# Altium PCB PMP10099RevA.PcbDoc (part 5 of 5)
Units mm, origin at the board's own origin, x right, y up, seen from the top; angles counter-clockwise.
Board outline 227.58 x 89.92 mm, 2 copper layers (Top Layer, Bottom Layer), stack 1.575 mm thick; 558 components, 261 nets, 1374 pads, 560 vias.
Unrouted connection lines stored in the file: 7.
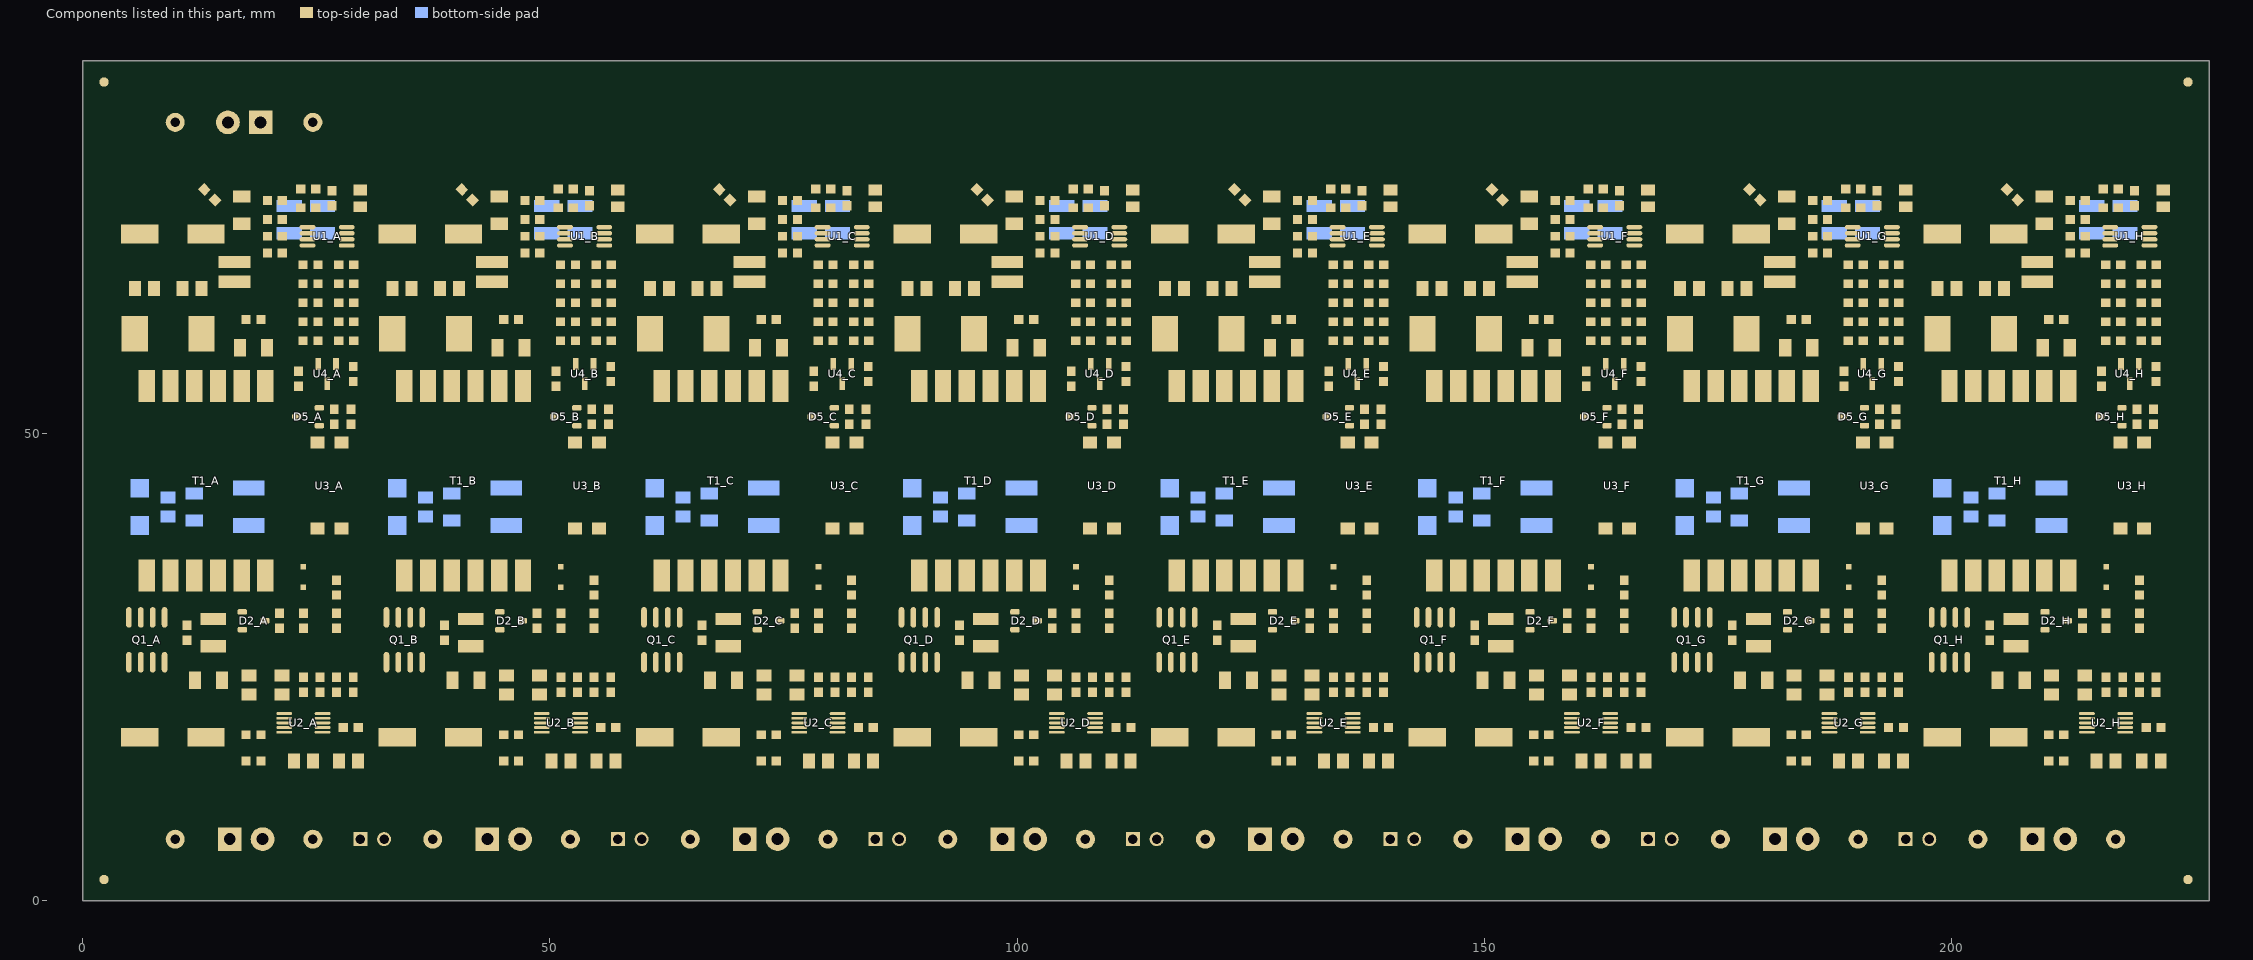
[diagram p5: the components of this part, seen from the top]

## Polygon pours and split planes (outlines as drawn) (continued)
RTN on Top Layer "Top Layer-No Net 18" (solid, remove dead copper, pour order 544): 182.88,3.048 195.834,3.048 195.834,12.446 181.864,12.446 181.864,17.526 175.514,17.526 175.514,9.906 182.88,9.906
VIN on Top Layer "Top Layer-No Net 19" (solid, remove dead copper, pour order 552): 182.372,3.048 182.372,9.398 174.498,9.398 174.498,13.208 169.418,13.208 169.418,3.048
RTN on Top Layer "Top Layer-No Net 13" (solid, remove dead copper, pour order 504): 183.896,36.83 183.896,30.988 185.928,30.988 185.928,30.226 187.452,30.226 187.452,34.544 189.992,34.544 189.992,36.83
NetC11_G_1 on Top Layer "Top Layer-No Net 12" (solid, remove dead copper, pour order 496): 189.992,29.718 185.42,29.718 185.42,30.48 183.896,30.48 183.896,27.94 189.992,27.94
NetC17_G_1 on Top Layer "Top Layer-No Net 15" (solid, remove dead copper, pour order 528): 189.992,30.226 189.992,34.036 187.96,34.036 187.96,30.226
VIN on Top Layer "Top Layer-No Net 14" (solid, remove dead copper, pour order 520): 169.418,21.59 174.498,21.59 174.498,12.954 169.418,12.954
NetD2_G_1 on Top Layer "Top Layer-No Net 11" (solid, remove dead copper, pour order 480): 181.356,36.83 181.356,29.972 183.388,29.972 183.388,36.83
NetQ1_G_4 on Top Layer "Top Layer-No Net 7" (solid, remove dead copper, pour order 416): 173.736,26.67 175.006,26.67 175.768,25.908 175.768,24.384 173.736,24.384
GND on Top Layer "Top Layer-No Net 4" (solid, remove dead copper, pour order 344): 183.896,53.086 186.69,53.086 186.69,66.294 183.896,66.294
NetC6_G_1 on Top Layer "Top Layer-No Net 3" (solid, remove dead copper, pour order 336): 183.388,67.564 183.388,73.406 180.848,73.406 180.848,76.073 179.705,76.073 177.038,73.406 175.006,73.406 175.006,68.58 178.816,68.58 179.832,67.564
GND on Top Layer "Top Layer-No Net 5" (solid, remove dead copper, pour order 352): 174.498,68.58 169.418,68.58 169.418,76.962 180.848,76.962 180.848,76.454 179.578,76.454 177.038,73.914 174.498,73.914
NetC7_G_1 on Top Layer "Top Layer-No Net 2" (solid, remove dead copper, pour order 328): 183.388,57.658 173.99,57.658 173.99,62.738 175.768,62.738 177.292,64.262 177.292,67.056 183.388,67.056
RTN on Top Layer "Top Layer-No Net 16" (solid, remove dead copper, pour order 536): 187.96,19.685 187.96,19.431 185.42,19.431 185.42,19.05 183.388,19.05 183.388,17.272 180.086,17.272 180.086,20.828 185.42,20.828 185.42,19.685
RTN on Top Layer "Top Layer-No Net 10" (solid, remove dead copper, pour order 464): 175.768,28.448 183.642,28.448 183.642,26.416 181.102,26.416 181.102,12.954 175.514,12.954 175.514,21.59 178.562,21.59 178.562,25.908 177.8,26.67 176.276,26.67 175.768,27.178
VIN on Top Layer "Top Layer-No Net 9" (solid, remove dead copper, pour order 448): 175.768,38.608 178.816,38.608 178.816,37.338 178.308,36.83 178.308,32.766 178.562,32.512 181.102,32.512 181.102,28.956 175.768,28.956 175.768,32.512 176.022,32.512 176.276,32.766 176.276,36.83 175.768,37.338
GND on Top Layer "Top Layer-No Net 17" (solid, remove dead copper, pour order 488): 186.69,53.594 186.69,46.482 185.166,44.958 181.102,44.958 181.102,48.26 183.896,51.054 183.896,53.594
NetD1_G_2 on Top Layer "Top Layer-No Net 6" (solid, remove dead copper, pour order 392): 173.228,38.608 173.228,32.766 173.482,32.512 174.752,32.512 174.752,28.448 169.672,28.448 169.672,32.512 170.18,32.512 170.434,32.766 170.434,38.608
NetQ1_G_1 on Top Layer "Top Layer-No Net 8" (solid, remove dead copper, pour order 432): 173.228,27.432 173.228,24.13 173.482,23.876 176.022,23.876 176.276,24.13 176.276,25.908 178.054,25.908 178.054,22.098 169.672,22.098 169.672,27.432
RTN on Top Layer "Top Layer-No Net 20" (solid, remove dead copper, pour order 296): 187.452,40.64 187.452,37.338 190.5,37.338 190.5,26.416 189.865,25.781 189.865,23.368 195.199,23.368 195.199,40.64
GND on Top Layer "Top Layer-No Net 21" (solid, remove dead copper, pour order 304): 195.326,48.26 195.326,67.056 187.198,67.056 187.198,48.26
NetC5_H_1 on Top Layer "Top Layer-No Net 1" (solid, remove dead copper, pour order 319): 199.771,67.056 204.343,67.056 204.343,64.516 204.089,64.262 200.025,64.262 199.771,64.516
NetC5_H_2 on Top Layer "Top Layer-No Net" (solid, remove dead copper, pour order 311): 200.787,53.086 200.787,62.738 199.263,64.262 199.263,67.056 196.977,67.056 196.977,53.086
RTN on Top Layer "Top Layer-No Net 18" (solid, remove dead copper, pour order 543): 210.439,3.048 223.393,3.048 223.393,12.446 209.423,12.446 209.423,17.526 203.073,17.526 203.073,9.906 210.439,9.906
VIN on Top Layer "Top Layer-No Net 19" (solid, remove dead copper, pour order 551): 209.931,3.048 209.931,9.398 202.057,9.398 202.057,13.208 196.977,13.208 196.977,3.048
RTN on Top Layer "Top Layer-No Net 13" (solid, remove dead copper, pour order 503): 211.455,36.83 211.455,30.988 213.487,30.988 213.487,30.226 215.011,30.226 215.011,34.544 217.551,34.544 217.551,36.83
NetC11_H_1 on Top Layer "Top Layer-No Net 12" (solid, remove dead copper, pour order 495): 217.551,29.718 212.979,29.718 212.979,30.48 211.455,30.48 211.455,27.94 217.551,27.94
NetC17_H_1 on Top Layer "Top Layer-No Net 15" (solid, remove dead copper, pour order 527): 217.551,30.226 217.551,34.036 215.519,34.036 215.519,30.226
VIN on Top Layer "Top Layer-No Net 14" (solid, remove dead copper, pour order 519): 196.977,21.59 202.057,21.59 202.057,12.954 196.977,12.954
NetD2_H_1 on Top Layer "Top Layer-No Net 11" (solid, remove dead copper, pour order 479): 208.915,36.83 208.915,29.972 210.947,29.972 210.947,36.83
NetQ1_H_4 on Top Layer "Top Layer-No Net 7" (solid, remove dead copper, pour order 415): 201.295,26.67 202.565,26.67 203.327,25.908 203.327,24.384 201.295,24.384
GND on Top Layer "Top Layer-No Net 4" (solid, remove dead copper, pour order 343): 211.455,53.086 214.249,53.086 214.249,66.294 211.455,66.294
NetC6_H_1 on Top Layer "Top Layer-No Net 3" (solid, remove dead copper, pour order 335): 210.947,67.564 210.947,73.406 208.407,73.406 208.407,76.073 207.264,76.073 204.597,73.406 202.565,73.406 202.565,68.58 206.375,68.58 207.391,67.564
GND on Top Layer "Top Layer-No Net 5" (solid, remove dead copper, pour order 351): 202.057,68.58 196.977,68.58 196.977,76.962 208.407,76.962 208.407,76.454 207.137,76.454 204.597,73.914 202.057,73.914
NetC7_H_1 on Top Layer "Top Layer-No Net 2" (solid, remove dead copper, pour order 327): 210.947,57.658 201.549,57.658 201.549,62.738 203.327,62.738 204.851,64.262 204.851,67.056 210.947,67.056
RTN on Top Layer "Top Layer-No Net 16" (solid, remove dead copper, pour order 535): 215.519,19.685 215.519,19.431 212.979,19.431 212.979,19.05 210.947,19.05 210.947,17.272 207.645,17.272 207.645,20.828 212.979,20.828 212.979,19.685
RTN on Top Layer "Top Layer-No Net 10" (solid, remove dead copper, pour order 463): 203.327,28.448 211.201,28.448 211.201,26.416 208.661,26.416 208.661,12.954 203.073,12.954 203.073,21.59 206.121,21.59 206.121,25.908 205.359,26.67 203.835,26.67 203.327,27.178
VIN on Top Layer "Top Layer-No Net 9" (solid, remove dead copper, pour order 447): 203.327,38.608 206.375,38.608 206.375,37.338 205.867,36.83 205.867,32.766 206.121,32.512 208.661,32.512 208.661,28.956 203.327,28.956 203.327,32.512 203.581,32.512 203.835,32.766 203.835,36.83 203.327,37.338
GND on Top Layer "Top Layer-No Net 17" (solid, remove dead copper, pour order 487): 214.249,53.594 214.249,46.482 212.725,44.958 208.661,44.958 208.661,48.26 211.455,51.054 211.455,53.594
NetD1_H_2 on Top Layer "Top Layer-No Net 6" (solid, remove dead copper, pour order 391): 200.787,38.608 200.787,32.766 201.041,32.512 202.311,32.512 202.311,28.448 197.231,28.448 197.231,32.512 197.739,32.512 197.993,32.766 197.993,38.608
NetQ1_H_1 on Top Layer "Top Layer-No Net 8" (solid, remove dead copper, pour order 431): 200.787,27.432 200.787,24.13 201.041,23.876 203.581,23.876 203.835,24.13 203.835,25.908 205.613,25.908 205.613,22.098 197.231,22.098 197.231,27.432
RTN on Top Layer "Top Layer-No Net 20" (solid, remove dead copper, pour order 295): 215.011,40.64 215.011,37.338 218.059,37.338 218.059,26.416 217.424,25.781 217.424,23.368 222.758,23.368 222.758,40.64
GND on Top Layer "Top Layer-No Net 21" (solid, remove dead copper, pour order 303): 222.885,48.26 222.885,67.056 214.757,67.056 214.757,48.26
NetC5_B_1 on Top Layer "Top Layer-No Net 1" (solid, remove dead copper, pour order 318): 34.417,67.056 38.989,67.056 38.989,64.516 38.735,64.262 34.671,64.262 34.417,64.516
NetC5_B_2 on Top Layer "Top Layer-No Net" (solid, remove dead copper, pour order 310): 35.433,53.086 35.433,62.738 33.909,64.262 33.909,67.056 31.623,67.056 31.623,53.086
RTN on Top Layer "Top Layer-No Net 18" (solid, remove dead copper, pour order 542): 45.085,3.048 58.039,3.048 58.039,12.446 44.069,12.446 44.069,17.526 37.719,17.526 37.719,9.906 45.085,9.906
VIN on Top Layer "Top Layer-No Net 19" (solid, remove dead copper, pour order 550): 44.577,3.048 44.577,9.398 36.703,9.398 36.703,13.208 31.623,13.208 31.623,3.048
RTN on Top Layer "Top Layer-No Net 13" (solid, remove dead copper, pour order 502): 46.101,36.83 46.101,30.988 48.133,30.988 48.133,30.226 49.657,30.226 49.657,34.544 52.197,34.544 52.197,36.83
NetC11_B_1 on Top Layer "Top Layer-No Net 12" (solid, remove dead copper, pour order 494): 52.197,29.718 47.625,29.718 47.625,30.48 46.101,30.48 46.101,27.94 52.197,27.94
NetC17_B_1 on Top Layer "Top Layer-No Net 15" (solid, remove dead copper, pour order 526): 52.197,30.226 52.197,34.036 50.165,34.036 50.165,30.226
VIN on Top Layer "Top Layer-No Net 14" (solid, remove dead copper, pour order 518): 31.623,21.59 36.703,21.59 36.703,12.954 31.623,12.954
NetD2_B_1 on Top Layer "Top Layer-No Net 11" (solid, remove dead copper, pour order 478): 43.561,36.83 43.561,29.972 45.593,29.972 45.593,36.83
NetQ1_B_4 on Top Layer "Top Layer-No Net 7" (solid, remove dead copper, pour order 414): 35.941,26.67 37.211,26.67 37.973,25.908 37.973,24.384 35.941,24.384
GND on Top Layer "Top Layer-No Net 4" (solid, remove dead copper, pour order 342): 46.101,53.086 48.895,53.086 48.895,66.294 46.101,66.294
NetC6_B_1 on Top Layer "Top Layer-No Net 3" (solid, remove dead copper, pour order 334): 45.593,67.564 45.593,73.406 43.053,73.406 43.053,76.073 41.91,76.073 39.243,73.406 37.211,73.406 37.211,68.58 41.021,68.58 42.037,67.564
GND on Top Layer "Top Layer-No Net 5" (solid, remove dead copper, pour order 350): 36.703,68.58 31.623,68.58 31.623,76.962 43.053,76.962 43.053,76.454 41.783,76.454 39.243,73.914 36.703,73.914
NetC7_B_1 on Top Layer "Top Layer-No Net 2" (solid, remove dead copper, pour order 326): 45.593,57.658 36.195,57.658 36.195,62.738 37.973,62.738 39.497,64.262 39.497,67.056 45.593,67.056
RTN on Top Layer "Top Layer-No Net 16" (solid, remove dead copper, pour order 534): 50.165,19.685 50.165,19.431 47.625,19.431 47.625,19.05 45.593,19.05 45.593,17.272 42.291,17.272 42.291,20.828 47.625,20.828 47.625,19.685
RTN on Top Layer "Top Layer-No Net 10" (solid, remove dead copper, pour order 462): 37.973,28.448 45.847,28.448 45.847,26.416 43.307,26.416 43.307,12.954 37.719,12.954 37.719,21.59 40.767,21.59 40.767,25.908 40.005,26.67 38.481,26.67 37.973,27.178
VIN on Top Layer "Top Layer-No Net 9" (solid, remove dead copper, pour order 446): 37.973,38.608 41.021,38.608 41.021,37.338 40.513,36.83 40.513,32.766 40.767,32.512 43.307,32.512 43.307,28.956 37.973,28.956 37.973,32.512 38.227,32.512 38.481,32.766 38.481,36.83 37.973,37.338
GND on Top Layer "Top Layer-No Net 17" (solid, remove dead copper, pour order 486): 48.895,53.594 48.895,46.482 47.371,44.958 43.307,44.958 43.307,48.26 46.101,51.054 46.101,53.594
NetD1_B_2 on Top Layer "Top Layer-No Net 6" (solid, remove dead copper, pour order 390): 35.433,38.608 35.433,32.766 35.687,32.512 36.957,32.512 36.957,28.448 31.877,28.448 31.877,32.512 32.385,32.512 32.639,32.766 32.639,38.608
NetQ1_B_1 on Top Layer "Top Layer-No Net 8" (solid, remove dead copper, pour order 430): 35.433,27.432 35.433,24.13 35.687,23.876 38.227,23.876 38.481,24.13 38.481,25.908 40.259,25.908 40.259,22.098 31.877,22.098 31.877,27.432
RTN on Top Layer "Top Layer-No Net 20" (solid, remove dead copper, pour order 294): 49.657,40.64 49.657,37.338 52.705,37.338 52.705,26.416 52.07,25.781 52.07,23.368 57.404,23.368 57.404,40.64
GND on Top Layer "Top Layer-No Net 21" (solid, remove dead copper, pour order 302): 57.531,48.26 57.531,67.056 49.403,67.056 49.403,48.26
VOUT on Top Layer "Top Overlay-No Net" (solid, remove dead copper, pour order 292): 16.002,74.422 18.034,74.422 18.034,86.868 16.002,86.868
VOUT on Top Layer "Top Overlay-No Net" (solid, remove dead copper, pour order 565): 43.561,74.422 45.593,74.422 45.593,86.868 43.561,86.868
VOUT on Top Layer "Top Overlay-No Net" (solid, remove dead copper, pour order 566): 71.12,74.422 73.152,74.422 73.152,86.868 71.12,86.868
VOUT on Top Layer "Top Overlay-No Net" (solid, remove dead copper, pour order 567): 98.679,74.422 100.711,74.422 100.711,86.868 98.679,86.868
VOUT on Top Layer "Top Overlay-No Net" (solid, remove dead copper, pour order 568): 126.238,74.422 128.27,74.422 128.27,86.868 126.238,86.868
VOUT on Top Layer "Top Overlay-No Net" (solid, remove dead copper, pour order 569): 153.797,74.422 155.829,74.422 155.829,86.868 153.797,86.868
VOUT on Top Layer "Top Overlay-No Net" (solid, remove dead copper, pour order 570): 181.356,74.422 183.388,74.422 183.388,86.868 181.356,86.868
VOUT on Top Layer "Top Overlay-No Net" (solid, remove dead copper, pour order 571): 208.915,74.422 210.947,74.422 210.947,86.868 208.915,86.868
VOUT on Top Layer "Top Layer-No Net 22" (solid, pour order 572): 4.064,86.868 4.064,78.74 223.393,78.74 223.393,86.868

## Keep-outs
Keep-Out Layer:
  text ".Layer_Name" at 14.656,-21.806 h1.52

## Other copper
Top Layer:
  text ".Layer_Name" at 14.656,-21.806 h1.52
Bottom Layer:
  text ".Layer_Name" at 14.656,-21.806 h1.52

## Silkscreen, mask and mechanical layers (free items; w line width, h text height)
Top Overlay:
  lines w0.178: 3.81,12.446 30.734,12.446 30.734,77.216 3.81,77.216 3.81,12.446 ; 31.369,12.446 31.369,77.216 58.293,77.216 58.293,12.446 31.369,12.446 ; 58.928,12.446 58.928,77.216 85.852,77.216 85.852,12.446 58.928,12.446 ; 86.487,12.446 86.487,77.216 113.411,77.216 113.411,12.446 86.487,12.446 ; 114.046,12.446 114.046,77.216 140.97,77.216 140.97,12.446 114.046,12.446 ; 141.605,12.446 141.605,77.216 168.529,77.216 168.529,12.446 141.605,12.446 ; 169.164,12.446 169.164,77.216 196.088,77.216 196.088,12.446 169.164,12.446 ; 196.723,12.446 196.723,77.216 223.647,77.216 223.647,12.446 196.723,12.446
  text ".Layer_Name" at 14.656,-21.806 h1.52
Bottom Overlay:
  text ".Layer_Name" at 14.656,-21.806 h1.52
Top Paste:
  text ".Layer_Name" at 14.656,-21.806 h1.52
Bottom Paste:
  text ".Layer_Name" at 14.656,-21.806 h1.52
Top Solder:
  text "PMP10099" at 202.184,82.296 h2.54
  text ".Layer_Name" at 14.656,-21.806 h1.52
  text ".Layer_Name" at 14.656,-21.806 h1.52
Bottom Solder:
  circle w0.254: c219.329,82.804 r2.032
  circle w0.381: c220.218,83.439 r0.127
  circle w0.381: c218.567,83.439 r0.127
  lines w0.254: 218.227,81.915 218.481,82.169 ; 218.399,82.042 ccw(c219.372,82.858) 220.345,82.042 ; 220.218,82.169 220.472,81.915
  text ".Layer_Name" at 14.656,-21.806 h1.52
Drill Guide:
  text ".Layer_Name" at 14.656,-21.806 h1.52
M1 Board Outline:
  lines w0.5: -0.25,0 ccw(c0,0) 0,-0.25 ; -0.25,0 ccw(c0,0) 0,-0.25 ; -0.25,0 -0.25,89.916 ; -0.25,89.916 cw(c0,89.916) 0,90.166 ; -0.25,89.916 cw(c0,89.916) 0,90.166 ; 0,-0.25 227.584,-0.25 ; 0,90.166 227.584,90.166 ; 227.584,-0.25 ccw(c227.584,0) 227.834,0 ; 227.584,-0.25 ccw(c227.584,0) 227.834,0 ; 227.584,90.166 cw(c227.584,89.916) 227.834,89.916 ; 227.584,90.166 cw(c227.584,89.916) 227.834,89.916 ; 227.834,0 227.834,89.916
  text ".Layer_Name" at 14.656,-21.806 h1.52
M2 Board Dimensions:
  text ".Layer_Name" at 14.656,-21.806 h1.52
M3 3D STEP Top:
  text ".Layer_Name" at 14.656,-21.806 h1.52
M4 3D STEP Bottom:
  text ".Layer_Name" at 14.656,-21.806 h1.52
M5 Assembly Top:
  lines w0.254: -7.417,-23.626 160.223,-23.626 ; -7.417,-18.462 160.274,-18.462 ; -7.417,-13.297 -7.417,-28.791 94.31,-28.791 160.274,-28.791 160.274,-13.297 -7.404,-13.297 -7.404,-28.791 32.614,-28.791 ; 55.194,-28.791 55.194,-13.297 ; 87.376,-18.462 87.376,-13.297 ; 108.712,-18.462 108.712,-13.297 ; 124.511,-28.956 124.511,-23.804
  text "PCB VIEWED FROM TOP SIDE" at -5.804,-16.654 h1.52
  text "BOARD #:" at 57.099,-16.654 h1.52
  text ".PRJ_Number" at 70.955,-16.654 h1.52
  text "REV:" at 92.405,-16.654 h1.52
  text ".PCB_Rev" at 99.809,-16.654 h1.52
  text "SVN REV:" at 113.69,-16.654 h1.52
  text ".VersionControl_RevNumber" at 126.543,-16.654 h1.52
  text "IGNORE ->" at -5.804,-21.806 h1.52
  text "PLOT NAME =" at -5.804,-27.034 h1.52
  text ".plot_File_Name" at 14.656,-27.034 h1.52
  text "GENERATED    :" at 57.15,-27.034 h1.52
  text ".Print_Date" at 79.235,-27.034 h1.52
  text ".Print_Time" at 97.752,-27.034 h1.52
  text "TEXAS INSTRUMENTS" at 129.87,-27.034 h1.52
M6 Assembly Bottom:
  lines w0.254: -7.429,-18.474 160.261,-18.474 ; -7.379,-23.639 160.261,-23.639 ; 28.334,-28.969 28.334,-23.817 ; 44.133,-18.474 44.133,-13.31 ; 65.468,-18.474 65.468,-13.31 ; 97.65,-28.804 97.65,-13.31 ; 120.231,-28.804 160.249,-28.804 160.249,-13.31 -7.429,-13.31 -7.429,-28.804 58.534,-28.804 160.261,-28.804 160.261,-13.31
  text ".VersionControl_RevNumber" at 26.302,-16.667 h1.52
  text "SVN REV:" at 39.154,-16.667 h1.52
  text ".PCB_Rev" at 53.035,-16.667 h1.52
  text "REV:" at 60.439,-16.667 h1.52
  text ".PRJ_Number" at 81.89,-16.667 h1.52
  text "BOARD #:" at 95.745,-16.667 h1.52
  text "PCB VIEWED FROM BOTTOM SIDE" at 158.648,-16.667 h1.52
  text "IGNORE ->" at 64.715,-21.806 h1.52
  text "TEXAS INSTRUMENTS" at 22.974,-27.047 h1.52
  text ".Print_Time" at 55.093,-27.047 h1.52
  text ".Print_Date" at 73.609,-27.047 h1.52
  text "GENERATED    :" at 95.694,-27.047 h1.52
  text ".plot_File_Name" at 138.189,-27.047 h1.52
  text "PLOT NAME =" at 158.648,-27.047 h1.52
M9 Title Sheet:
  drawing of 57 lines, arcs and shapes, not listed
  text "1" at 18.792,204.127 h1.78
  text "2" at 82.182,204.127 h1.78
  text "3" at 145.411,204.127 h1.78
  text "4" at 209.08,204.127 h1.78
  text "5" at 272.555,204.127 h1.78
  text "6" at 336.182,204.127 h1.78
  text "A" at -10.579,175.095 h1.78
  text "A" at 365.341,175.095 h1.78
  text "B" at -10.579,114.643 h1.78
  text "B" at 365.341,114.643 h1.78
  text "C" at -10.579,54.318 h1.78
  text "C" at 365.341,54.318 h1.78
  text "PROJECT TITLE:" at 288.125,7.048 h1.14
  text ".PRJ_Title" at 289.395,3.662 h1.78
  text "DESIGNED FOR:" at 288.125,-0.597 h1.14
  text ".PRJ_Customer" at 289.395,-4.153 h1.78
  text "D" at -10.579,-5.88 h1.78
  text "D" at 365.341,-5.88 h1.78
  text "FILE NAME:" at 288.125,-8.217 h1.14
  text ".PCB_File_Name_No_Path" at 289.395,-11.265 h1.78
  text "Texas Instruments (TI) and/or its licensors do not warrant the accuracy or completeness of this specification" at 161.9,-15.376 h1.14
  text "ENGINEER:" at 288.125,-15.583 h1.14
  text "LAYOUT BY:" at 326.352,-15.583 h1.14
  text "or any information contained therein. TI and/or its licensors do not warrant that this design will meet" at 160.757,-18.237 h1.14
  text ".PRJ_Engineer" at 289.395,-19.52 h1.78
  text ".PCB_Layout" at 327.635,-19.52 h1.78
  text "the specifications, will be suitable for your application or fit for any particular purpose, or will operate in" at 160.757,-21.099 h1.14
  text ".Layer_Name" at 14.656,-21.806 h1.52
  text "ALTIUM DESIGNER VERSION:" at 326.352,-23.457 h1.14
  text "an implementation. TI and/or its licensors do not warrant that the design is production worthy. You should" at 160.757,-23.961 h1.14
  text "completely validate and test your design implementation to confirm the system functionality for your application." at 161.9,-26.822 h1.14
  text ".print_Scale" at 289.395,-26.843 h1.78
  text ".Application_BuildNumber" at 327.635,-26.843 h1.78
  text "1" at 18.792,-32.093 h1.78
  text "2" at 82.182,-32.093 h1.78
  text "3" at 145.411,-32.093 h1.78
  text "4" at 209.08,-32.093 h1.78
  text "5" at 272.555,-32.093 h1.78
  text "6" at 336.182,-32.093 h1.78
M10 Fab Notes:
  drawing of 212 lines, arcs and shapes, not listed
  text "DESIGN INFORMATION" at 314.478,172.974 h1.52
  text "(REFER ALSO ARRAY/PANEL PROFILING INFORMATION)" at 305.294,168.866 h1.52
  text "BOARD SIZE" at 287.87,168.758 h1.52
  text "3450MIL" at 299.613,165.511 h1.52
  text "4950MIL" at 318.333,165.511 h1.52
  text "Number of Layers :" at 298.106,160.503 h1.52
  text "2" at 325.914,160.249 h1.52
  text "MIN. TRACK WIDTH:" at 298.106,156.972 h1.52
  text "8" at 325.951,156.972 h1.52
  text "MIL" at 329.881,156.972 h1.52
  text "MIN. CLEARANCE:" at 298.106,153.619 h1.52
  text "8" at 325.951,153.619 h1.52
  text "MIL" at 329.881,153.619 h1.52
  text "MIN. VIA PAD SIZE:" at 298.106,150.266 h1.52
  text "24" at 325.189,150.266 h1.52
  text "MIL" at 329.881,150.266 h1.52
  text "0.05mm (2MIL)" at 315.759,146.667 h1.52
  text "MINIMUM ANNULAR RING" at 289.744,146.558 h1.52
  text "EXTERNAL" at 333.742,146.558 h1.52
  text "PER" at 294.824,143.561 h1.52
  text "IPC-D-275 CLASS 2 LEVEL C" at 300.412,143.561 h1.52
  text "MIL, HOLES" at 338.213,140.709 h1.52
  text "+/-" at 328.244,140.691 h1.52
  text "+/-" at 349.936,140.691 h1.52
  text "REGISTRATION TOLERANCES:" at 289.744,140.564 h1.52
  text "METAL" at 320.218,140.564 h1.52
  text "5" at 334.853,140.564 h1.52
  text "3" at 356.012,140.564 h1.52
  text "MIL" at 358.964,140.564 h1.52
  text "MATERIAL:" at 287.844,135.243 h1.52
  text "FR-4 High Tg" at 312.9,131.679 h1.52
  text "FR-408" at 298.538,131.461 h1.52
  text "OTHER" at 336.333,131.461 h1.52
  text "62 MIL (1.6mm) +/-10%" at 306.668,127.328 h1.52
  text "THICKNESS:" at 289.744,127.219 h1.52
  text "OTHER" at 339.305,127.219 h1.52
  text "TOLERANCE:" at 289.744,123.206 h1.52
  text "ANSI IPC-6012 TYPE 3 CLASS 2" at 315.81,123.206 h1.52
  text "OTHER +/-" at 315.81,119.244 h1.52
  text "BOW & TWIST:" at 289.744,115.256 h1.52
  text "ANSI IPC-6012 TYPE 3 CLASS 2" at 315.81,115.256 h1.52
  text "OTHER +/-" at 315.81,111.23 h1.52
  text "COPPER THICKNESS (FINISHED):" at 287.844,107.788 h1.52
  text "1.4MIL (1oz)" at 310.196,103.909 h1.52
  text "2MIL (1.4oz)" at 329.678,103.909 h1.52
  text "2.8MIL (2oz)" at 348.144,103.909 h1.52
  text "OUTER:" at 296.912,103.801 h1.52
  text "1.4MIL (1oz)" at 310.196,99.922 h1.52
  text "2.8MIL (2oz)" at 329.678,99.922 h1.52
  text "N/A" at 348.132,99.931 h1.52
  text "INNER SIGNAL:" at 289.57,99.813 h1.52
  text "DRILLING:" at 287.844,96.282 h1.52
  text "REFERENCE:" at 289.744,93.31 h1.52
  text "AS SHOWN" at 310.958,93.31 h1.52
  text "NC_DRILL FILES" at 332.574,93.31 h1.52
  text "PTH MIN COPPER THICKNESS:" at 289.744,89.297 h1.52
  text "1MIL" at 327.519,89.297 h1.52
  text "OTHER" at 340.143,89.297 h1.52
  text "BOARD FINISH:" at 287.844,85.259 h1.52
  text "SILKSCREEN:" at 291.787,82.261 h1.52
  text "TOP" at 319.086,82.261 h1.52
  text "BOTTOM" at 332.066,82.261 h1.52
  text "SILKSCREEN COLOR:" at 291.787,78.02 h1.52
  text "WHITE" at 319.086,78.02 h1.52
  text "OTHER" at 332.066,78.02 h1.52
  text "SOLDER RESIST COLOR:" at 291.787,73.702 h1.52
  text "X" at 212.72,73.24 h1.52 r90
  text "X" at 148.091,71.845 h1.52 r90
  text "X" at 156.041,71.845 h1.52 r90
  text "X" at 175.65,71.845 h1.52 r90
  text "X" at 183.6,71.845 h1.52 r90
  text "X" at 99.603,70.828 h1.52 r90
  text "X" at 193.303,69.785 h1.52 r90
  text "GREEN" at 309.434,69.658 h1.52
  text "BLUE" at 324.446,69.658 h1.52
  text "OTHER" at 338.111,69.658 h1.52
  text "X" at 118.018,67.753 h1.52 r90
  text "X" at 167.513,67.716 h1.52 r90
  text "X" at 195.072,67.716 h1.52 r90
  text "X" at 94.705,66.991 h1.52 r90
  text "X" at 124.52,66.991 h1.52 r90
  text "IMMERSION GOLD (ENIG)" at 314.794,64.87 h1.52
  text "ENEPIG" at 348.767,64.786 h1.52
  text "SURFACE FINISH:" at 287.844,64.761 h1.52
  text "X" at 144.078,64.196 h1.52 r90
  text "X" at 171.637,64.196 h1.52 r90
  text "IMM. TIN/SILVER OR EQUIV" at 296.215,60.773 h1.52
  text "OTHER" at 332.574,60.773 h1.52
  text "X" at 72.12,57.608 h1.52 r90
  text "X" at 99.679,57.608 h1.52 r90
  text "X" at 68.069,57.555 h1.52 r90
  text "X" at 95.628,57.555 h1.52 r90
  text "ARRAY/PANEL:" at 287.844,56.226 h1.52
  text "CUT AND TRIM PER MECH LAYER 1" at 314.794,56.118 h1.52
  text "N.C. ROUTE" at 314.794,52.264 h1.52
  text "V. SCORE" at 336.79,52.264 h1.52
  text "CERTIFICATION:" at 287.844,48.784 h1.52
  text "MATERIALS AND WORKMANSHIP FOR ALL PCBS" at 306.259,48.784 h1.52
  text "TO MEET OR EXCEED THE REQUIREMENTS OF:" at 306.259,46.295 h1.52
  text "ANSI IPC-A-600F CLASS ->" at 300.303,42.828 h1.52
  text "2" at 344.956,42.828 h1.52
  text "1" at 336.955,42.79 h1.52
  text "3" at 353.948,42.79 h1.52
  text "UL 94V-0" at 300.303,38.777 h1.52
  text "RoHS" at 320.928,38.777 h1.52
  text "OTHER" at 337.296,38.777 h1.52
  text "PER ORDER" at 347.381,38.777 h1.52
  text "ADDITIONAL REQUIREMENTS:" at 287.844,35.195 h1.52
  text "MICROSECTION:" at 289.744,32.274 h1.52
  text "YES" at 312.749,32.274 h1.52
  text "REQUIRED" at 334.631,28.308 h1.52
  text "BARE BOARD ELEC. TEST:" at 289.744,28.236 h1.52
  text "NONE" at 322.909,28.236 h1.52
  text "PER ORDER" at 349.668,28.236 h1.52
  text "MANUFACTURER'S UL:" at 289.744,24.248 h1.52
  text "RAIL" at 319.353,24.139 h1.52
  text "METAL" at 331.845,24.139 h1.52
  text "SILK" at 344.842,24.139 h1.52
  text ".Layer_Name" at 14.656,-21.806 h1.52
M11 Gerber Information:
  lines w0.254: -7.417,-23.626 160.223,-23.626 ; -7.417,-18.462 160.274,-18.462 ; -7.417,-13.297 -7.417,-28.791 94.31,-28.791 160.274,-28.791 160.274,-13.297 -7.404,-13.297 -7.404,-28.791 32.614,-28.791 ; 55.194,-28.791 55.194,-13.297 ; 87.376,-18.462 87.376,-13.297 ; 108.712,-18.462 108.712,-13.297 ; 124.511,-28.956 124.511,-23.804
  text "ALL ARTWORK VIEWED FROM TOP SIDE" at -5.804,-16.654 h1.52
  text "BOARD #:" at 57.099,-16.654 h1.52
  text ".PRJ_Number" at 70.955,-16.654 h1.52
  text "REV:" at 92.405,-16.654 h1.52
  text ".PCB_Rev" at 99.809,-16.654 h1.52
  text "SVN REV:" at 113.69,-16.654 h1.52
  text ".VersionControl_RevNumber" at 126.543,-16.654 h1.52
  text "LAYER NAME =" at -5.804,-21.806 h1.52
  text "PLOT NAME =" at -5.804,-27.034 h1.52
  text ".plot_File_Name" at 14.656,-27.034 h1.52
  text "GENERATED    :" at 57.15,-27.034 h1.52
  text ".Print_Date" at 79.235,-27.034 h1.52
  text ".Print_Time" at 97.752,-27.034 h1.52
  text "TEXAS INSTRUMENTS" at 129.87,-27.034 h1.52
M12 Stackup:
  lines w0.152: 201.066,47.803 ccw(c201.066,48.666) 201.93,48.666 ; 261.804,178.689 261.804,196.621 cw(c262.668,196.621) 262.668,197.485 ; 287.884,195.961 353.974,195.961 cw(c353.974,195.097) 354.838,195.097 354.838,177.165 ; 288.544,189.484 353.314,189.484 ; 288.544,192.136 353.314,192.136
  text "The Stackup Legend below this is static." at 294.78,200.012 h1.52
  text "If you change the stackup, update the Legend." at 295.034,197.726 h1.52
  text "Layer Stack Up Detail for: Ref_Design.PcbDoc" at 288.544,192.966 h1.45
  text "Layer" at 263.328,192.669 h0.61
  text "Name" at 263.328,191.45 h0.61
  text "Gerber" at 311.298,191.145 h0.61
  text "Copper" at 325.611,191.145 h0.61
  text "Dielectric" at 340.92,191.145 h0.61
  text "Document" at 311.298,189.926 h0.61
  text "Thickness" at 325.611,189.926 h0.61
  text "Material" at 340.92,189.926 h0.61
  text "Top Solder Mask" at 288.544,187.565 h0.86
  text "(.GTS)" at 311.298,187.565 h0.86
  text "Solder Resist" at 340.92,187.565 h0.86
  text "Top Layer" at 263.328,186.631 h0.86
  text "(.GTL)" at 311.298,185.107 h0.86
  text "1.4mil" at 325.611,185.107 h0.86
  text "FR-4" at 340.92,183.879 h0.86
  text "Bottom Layer" at 288.544,182.65 h0.86
  text "(.GBL)" at 311.298,182.65 h0.86
  text "1.4mil" at 325.611,182.65 h0.86
  text "(.GBS)" at 198.039,72.08 h0.86 r90
  text "Bottom Solder Mask" at 198.039,49.327 h0.86 r90
  text ".Layer_Name" at 14.656,-21.806 h1.52
M13 Component Bodies Top:
  text ".Layer_Name" at 14.656,-21.806 h1.52
M14 Component Bodies Bottom:
  text ".Layer_Name" at 14.656,-21.806 h1.52
M15 Courtyards Top:
  text ".Layer_Name" at 14.656,-21.806 h1.52
M16 Courtyards Bottom:
  text ".Layer_Name" at 14.656,-21.806 h1.52
Drill Drawing:
  text ".Layer_Name" at 14.656,-21.806 h1.52

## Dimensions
3.81,12.446 to 3.81,77.216 on Top Overlay
3.81,77.216 to 223.647,77.216 on Top Overlay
